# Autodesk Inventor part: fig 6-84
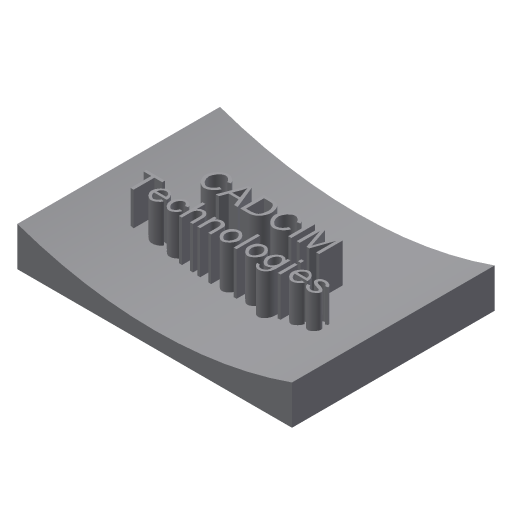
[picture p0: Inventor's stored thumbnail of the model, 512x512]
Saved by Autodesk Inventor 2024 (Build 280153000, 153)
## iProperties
Shininess: 64.0
Length Units: 11269
Angle Units: 11279
Time Units: 11290
Mass Units: 11283
Length Display Precision: 3
Angle Display Precision: 2
Compacted: True
Part Number: fig 6-84
Document SubType Name: Modeling
Created: 2002-12
Designer: deepak
Density: 1 g/cm^3
Material: Generic
Appearance: Default
Density: 0.0
Volumn: 0.0
Area: 0.0
PropertySet Name: Model Information
Control State: 0
Master: False
Checked Out: False
Author: deepak
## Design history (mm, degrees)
sketch "Sketch1"
  geometry: L1 (-39.922, 33.786)-(30.103, 33.786); L2 (30.103, 33.786)-(30.103, -17.894); L3 (30.103, -17.894)-(-39.922, -17.894); L4 (-39.922, -17.894)-(-39.922, 33.786)
  constraints: 8 end point, 2 parallel, 1 horizontal, 1 perpendicular
extrude "Extrusion1" new body sketch "Sketch1" distance "d0" = 10; taper "d1" = 0 deg
workplane "Work Plane1"
sketch "Sketch2"
  geometry: L1 (-37.656, 15.034)-(26.28, 15.034); L2 (26.28, 15.034)-(26.28, 10.168); L3 (26.28, 10.168)-(-37.656, 10.168); L4 (-37.656, 10.168)-(-37.656, 15.034)
  constraints: 2 other
sketch "Sketch3"
  geometry: L1 (70.026, 10)-(0, 10) reference; A1 r 105 centre (35.013, 108.99) between (0, 10) and (70.026, 10)
  constraints: 2 point on circle, 1 centre point
  dimensions: "d5" = 105 radius of A1
extrude "Extrusion2" cut sketch "Sketch3" extent not by distance; stored distance "d3" = 10; taper "d4" = 0 deg
emboss "Emboss4" sketch "Sketch2" dims "d14" = 1, "d15" = 0
body "Solid1"
other parameters: "d2" = 5
